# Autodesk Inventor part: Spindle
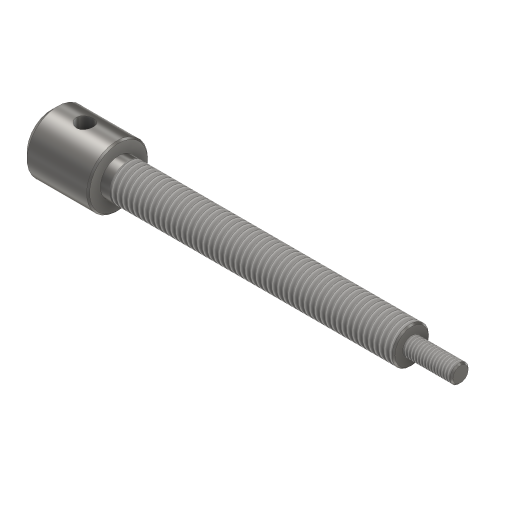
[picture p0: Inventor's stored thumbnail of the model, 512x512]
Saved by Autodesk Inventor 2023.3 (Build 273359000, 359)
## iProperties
Created: 2020-10
Part Number: Spindle
Material: Steel, Mild
Document SubType Name: Modeling
Designer: User
Density: 7.85 g/cm^3
Appearance: Semi-Polished
Mass: 137.528 g
Surface Area: 60.6766 cm^2
Volume: 17.5195 cm^3
Author: User
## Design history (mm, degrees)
sketch "Sketch1"
  geometry: L1 (0, 0)-(0, 8); L2 (2, 10)-(22, 10); L3 (22, 10)-(22, 6); L4 (118, 3)-(118, 6); L5 (118, 6)-(22, 6); L6 (118, 3)-(134, 3); L7 (134, 3)-(134, 0); L8 (0, 8)-(2, 10); L9 (134, 0)-(0, 0); 1 further point
  constraints: 18 end point, 4 perpendicular, 2 point on line, 1 horizontal, 1 vertical
  dimensions: "d6" = 2 distance of L1.end point (0, 10); "d7" = 2 distance of L2.start point (0, 10) (= d6); "d8" = 22 distance between parallel lines of L1 L3; "d9" = 96 distance of L4.end L3.end; "d10" = 16 distance of L4.start L6.end; "d11" = 10 distance between parallel lines of L9 L2; "d12" = 6 distance between parallel lines of L9 L5; "d13" = 3 distance between parallel lines of L9 L6
revolve "Revolution1" sketch "Sketch1" stored, may be unused: angle "d14" = 90 deg
sketch "Sketch2"
  geometry: L1 (0, -8)-(0, 8) reference; C1 r 2.75 at (11, 0); 1 further point
  constraints: 1 centre point
  dimensions: "d15" = 5.5 diameter of C1; "d16" = 11 distance from line of L1 C1.centre
extrude "Extrusion1" cut sketch "Sketch2" extent not by distance; stored distance "d17" = 10; taper "d18" = 0 deg
thread "Thread1" dims "d19" = 93, "d20" = 0
thread "Thread2" dims "d21" = 16, "d22" = 0
chamfer "Smusso1" distance "d23" = 0.5; stored, may be unused: second distance "d24" = 2, angle "d25" = 45 deg
chamfer "Smusso2" distance "d26" = 0.5; stored, may be unused: second distance "d27" = 2, angle "d28" = 45 deg
chamfer "Smusso3" distance "d29" = 0.5; stored, may be unused: second distance "d30" = 2, angle "d31" = 45 deg
body "Solid1"
